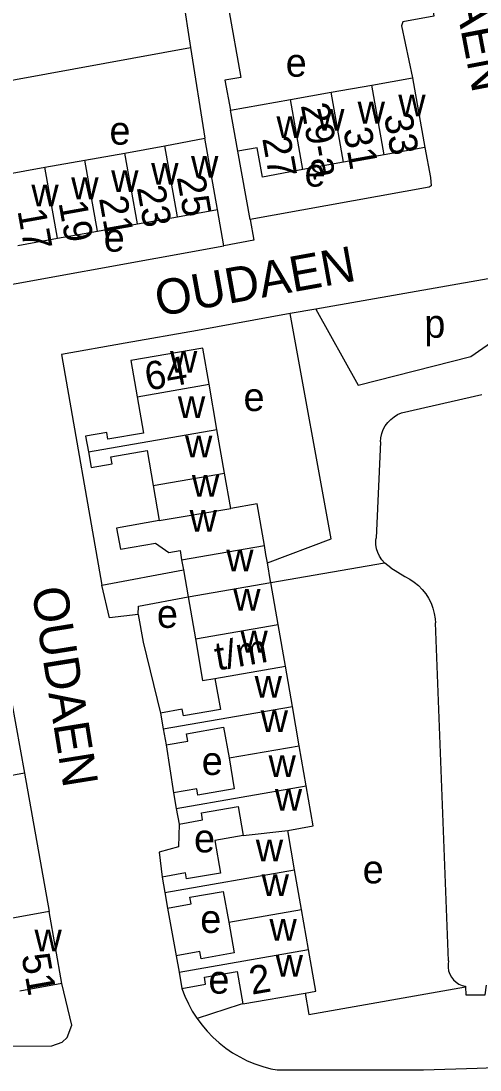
# Model space of a CAD drawing. Extents: x 157794 to 159375, y 380877 to 382306.
# Drawn here: x 158443.4 to 158508.3, y 381266.1 to 381414.5 of the extents above; entities that cross this region are included whole.
import ezdxf

# ---------------------------------------------------------------- set-up
doc = ezdxf.new("R2010")
doc.units = 0
for name, color, linetype in [('BLT_Basislijn', 7, 'Continuous'), ('BLT_Bebouwing', 7, 'Continuous'), ('BLT_Centroide', 7, 'Continuous'), ('BLT_Huisnummer', 7, 'Continuous'), ('BLT_Huisnummer_ tussenligend', 7, 'Continuous'), ('BLT_Huisnummer_reeks', 7, 'Continuous'), ('BLT_Onderverdeling_panden', 7, 'Continuous'), ('BLT_Straatnaam', 7, 'Continuous')]:
    doc.layers.add(name, color=color, linetype=linetype)

msp = doc.modelspace()

# ---------------------------------------------------------------- linework, layer by layer
at = {"layer": 'BLT_Basislijn'}
for p, q in [((158465.74, 381421.18), (158467.36, 381410.72)), ((158467.36, 381410.72), (158469.35, 381397.88)), ((158475.79, 381386.39), (158474.04, 381396.04)), ((158472.07, 381382.65), (158471.15, 381387.8)), ((158509.46, 381378.03), (158485.08, 381373.71)), ((158485.08, 381373.71), (158481.45, 381373.09)), ((158497.19, 381359.04), (158508.53, 381361.64)), ((158494.21, 381354.94), (158493.59, 381341.35)), ((158478.71, 381335.05), (158494.77, 381337.86)), ((158495.69, 381337.15), (158497.67, 381335.92)), ((158454.79, 381334.67), (158466.33, 381336.85)), ((158503.84, 381281.57), (158501.99, 381329.37)), ((158442.03, 381318.28), (158443.84, 381308.11)), ((158463.88, 381312.12), (158464.95, 381305.32)), ((158443.84, 381308.11), (158386.88, 381297.83)), ((158443.84, 381308.11), (158447.34, 381288.52)), ((158464.08, 381289.03), (158465.32, 381282.29)), ((158506.24, 381277.98), (158506.24, 381277.88))]:
    msp.add_line(p, q, dxfattribs=at)
for points in [[(158500.87, 381421.37), (158501.78, 381415.14), (158497.38, 381414.35), (158497.19, 381413.77), (158498.73, 381406.43)], [(158472.71, 381416.28), (158474.45, 381406.5), (158472.22, 381406.1), (158472.99, 381401.84)], [(158422.02, 381402.51), (158422.16, 381402.47), (158467.36, 381410.72)], [(158500.5, 381396.58), (158501.28, 381392.33), (158501.37, 381391.14), (158501.12, 381390.98), (158475.79, 381386.39)], [(158475.79, 381386.39), (158476.32, 381383.48), (158472.07, 381382.65)], [(158433.33, 381372.63), (158433.01, 381375.62), (158472.07, 381382.65)], [(158481.45, 381373.09), (158468.32, 381370.71), (158458.11, 381368.93), (158449.11, 381367.29), (158454.79, 381334.67)], [(158478.22, 381337.84), (158487.26, 381341.23), (158481.45, 381373.09)], [(158485.08, 381373.71), (158491.07, 381362.99), (158507.01, 381367.04), (158515.5, 381372.92)], [(158494.21, 381354.94), (158494.27, 381355.54), (158494.4, 381356.12), (158494.61, 381356.68), (158494.9, 381357.2), (158495.25, 381357.69), (158495.66, 381358.12), (158496.13, 381358.49), (158496.64, 381358.8), (158497.19, 381359.04)], [(158494.77, 381337.86), (158494.39, 381338.29), (158494.08, 381338.77), (158493.84, 381339.29), (158493.67, 381339.85), (158493.57, 381340.42), (158493.56, 381340.99), (158493.59, 381341.35)], [(158495.69, 381337.15), (158494.84, 381337.8), (158494.77, 381337.86)], [(158497.67, 381335.92), (158498.35, 381335.56), (158498.99, 381335.13), (158499.59, 381334.64), (158500.12, 381334.09), (158500.61, 381333.48), (158501.02, 381332.83), (158501.37, 381332.14), (158501.64, 381331.42), (158501.83, 381330.67), (158501.95, 381329.91), (158501.99, 381329.37)], [(158459.96, 381330.54), (158455.86, 381330.06), (158454.79, 381334.67)], [(158459.96, 381330.54), (158459.99, 381331.72), (158467, 381333.02)], [(158459.96, 381330.54), (158460.66, 381326.63), (158463.09, 381316.6)], [(158465.72, 381300.91), (158465.66, 381297.67), (158462.9, 381296.93), (158463.31, 381293.42)], [(158503.84, 381281.57), (158503.77, 381281.09), (158503.77, 381280.61), (158503.85, 381280.13), (158504.02, 381279.67), (158504.25, 381279.25), (158504.55, 381278.87), (158504.91, 381278.54), (158505.32, 381278.28), (158505.76, 381278.09), (158506.24, 381277.98)], [(158391.85, 381269.33), (158447.71, 381269.54), (158449.17, 381270.08), (158449.9, 381270.72), (158450.54, 381272.47), (158449.15, 381278.34)], [(158466.12, 381277.67), (158466.54, 381276.56), (158467.04, 381275.49), (158467.6, 381274.45), (158468.23, 381273.45), (158468.28, 381273.4)], [(158483.58, 381277.01), (158484.1, 381274), (158506.24, 381277.88)], [(158506.24, 381277.88), (158506.31, 381276.75), (158507.67, 381276.75)], [(158507.67, 381276.75), (158509.02, 381276.75), (158509.19, 381278.13)], [(158474.73, 381275.47), (158474.35, 381275.4), (158468.28, 381273.4)], [(158468.28, 381273.4), (158468.93, 381272.5), (158469.69, 381271.6), (158470.52, 381270.75), (158471.39, 381269.96), (158472.32, 381269.23), (158473.3, 381268.57), (158474.32, 381267.97), (158475.37, 381267.44), (158476.46, 381266.99), (158477.58, 381266.61), (158478.72, 381266.3), (158479.58, 381266.13)], [(158479.58, 381266.13), (158500.32, 381266.13), (158507.88, 381266.39)], [(158507.88, 381266.39), (158515.62, 381266.66)]]:
    msp.add_lwpolyline(points, dxfattribs=at)
at = {"layer": 'BLT_Bebouwing'}
for p, q in [((158487.24, 381404.38), (158492.99, 381405.4)), ((158492.99, 381405.4), (158498.73, 381406.43)), ((158498.73, 381406.43), (158500.5, 381396.58)), ((158481.49, 381403.35), (158487.24, 381404.38)), ((158472.99, 381401.84), (158481.49, 381403.35)), ((158474.04, 381396.04), (158472.99, 381401.84)), ((158463.71, 381396.81), (158469.35, 381397.88)), ((158471.15, 381387.8), (158469.35, 381397.88)), ((158458.06, 381395.8), (158463.71, 381396.81)), ((158500.5, 381396.58), (158494.75, 381395.55)), ((158446.75, 381393.78), (158452.4, 381394.79)), ((158452.4, 381394.79), (158458.06, 381395.8)), ((158494.75, 381395.55), (158489, 381394.52)), ((158441.1, 381392.77), (158446.75, 381393.78)), ((158489, 381394.52), (158483.25, 381393.49)), ((158465.5, 381386.79), (158471.15, 381387.8)), ((158459.85, 381385.78), (158465.5, 381386.79)), ((158448.55, 381383.75), (158454.2, 381384.77)), ((158454.2, 381384.77), (158459.85, 381385.78)), ((158442.9, 381382.74), (158448.55, 381383.75)), ((158471.08, 381356.72), (158469.97, 381363.09)), ((158472.16, 381350.53), (158471.08, 381356.72)), ((158473.03, 381345.55), (158472.16, 381350.53)), ((158462.05, 381348.77), (158462.91, 381343.82)), ((158478.01, 381339.03), (158477.8, 381340.28)), ((158478.22, 381337.84), (158478.01, 381339.03)), ((158466.08, 381338.28), (158466.33, 381336.85)), ((158478.68, 381335.22), (158478.22, 381337.84)), ((158466.33, 381336.85), (158467, 381333.02)), ((158478.71, 381335.05), (158478.68, 381335.22)), ((158479.74, 381329.14), (158478.71, 381335.05)), ((158467, 381333.02), (158468.03, 381327.1)), ((158480.77, 381323.23), (158479.74, 381329.14)), ((158481.76, 381317.54), (158480.77, 381323.23)), ((158463.09, 381316.6), (158463.48, 381314.36)), ((158482.73, 381311.98), (158481.76, 381317.54)), ((158463.48, 381314.36), (158463.88, 381312.12)), ((158483.72, 381306.32), (158482.73, 381311.98)), ((158464.95, 381305.32), (158465.33, 381303.11)), ((158465.33, 381303.11), (158465.72, 381300.91)), ((158482.06, 381294.43), (158481.09, 381300.01)), ((158483.04, 381288.82), (158482.06, 381294.43)), ((158463.31, 381293.42), (158463.69, 381291.23)), ((158463.69, 381291.23), (158464.08, 381289.03)), ((158447.34, 381288.52), (158441.39, 381287.46)), ((158449.15, 381278.34), (158447.34, 381288.52)), ((158484.02, 381283.16), (158483.04, 381288.82)), ((158465.32, 381282.29), (158465.72, 381279.98)), ((158465.72, 381279.98), (158466.12, 381277.67)), ((158449.15, 381278.34), (158443.21, 381277.28)), ((158474.73, 381275.47), (158483.58, 381277.01))]:
    msp.add_line(p, q, dxfattribs=at)
for points in [[(158483.25, 381393.49), (158477.52, 381392.38), (158476.77, 381396.55), (158474.04, 381396.04)], [(158469.97, 381363.09), (158469.08, 381368.21), (158458.91, 381366.44), (158459.8, 381361.32)], [(158459.8, 381361.32), (158460.69, 381356.19), (158455.67, 381355.32), (158455.5, 381356.28), (158452.5, 381355.76), (158452.89, 381353.54)], [(158452.89, 381353.54), (158453.27, 381351.33), (158456.26, 381351.85), (158456.09, 381352.83), (158461.19, 381353.72), (158462.05, 381348.77)], [(158477.8, 381340.28), (158476.76, 381346.2), (158473.03, 381345.55)], [(158462.91, 381343.82), (158456.89, 381342.77), (158457.42, 381339.76), (158462.38, 381340.62), (158464.28, 381339.31), (158465.86, 381339.58), (158466.08, 381338.28)], [(158468.03, 381327.1), (158469.06, 381321.19), (158470.8, 381321.5)], [(158470.8, 381321.5), (158471.57, 381317.1), (158466.34, 381316.19), (158466.17, 381317.14), (158463.09, 381316.6)], [(158463.88, 381312.12), (158466.96, 381312.65), (158466.78, 381313.68), (158472.03, 381314.6), (158472.79, 381310.25)], [(158472.79, 381310.25), (158473.54, 381305.9), (158468.39, 381305.01), (158468.24, 381305.89), (158464.95, 381305.32)], [(158481.09, 381300.01), (158484.71, 381300.64), (158483.72, 381306.32)], [(158465.72, 381300.91), (158469.06, 381301.49), (158468.89, 381302.49), (158474.1, 381303.4), (158474.81, 381299.31)], [(158474.81, 381299.31), (158470.77, 381298.6), (158471.58, 381293.98), (158466.77, 381293.14), (158466.62, 381294), (158463.31, 381293.42)], [(158464.08, 381289.03), (158467.42, 381289.61), (158467.26, 381290.55), (158471.98, 381291.38), (158472.74, 381287.03)], [(158472.74, 381287.03), (158473.5, 381282.68), (158468.84, 381281.87), (158468.66, 381282.88), (158465.32, 381282.29)], [(158483.58, 381277.01), (158485.05, 381277.26), (158484.02, 381283.16)], [(158466.12, 381277.67), (158469.47, 381278.25), (158469.3, 381279.25), (158473.93, 381280.06), (158474.73, 381275.47)]]:
    msp.add_lwpolyline(points, dxfattribs=at)
at = {"layer": 'BLT_Onderverdeling_panden'}
for p, q in [((158494.75, 381395.55), (158492.99, 381405.4)), ((158489, 381394.52), (158487.24, 381404.38)), ((158483.25, 381393.49), (158481.49, 381403.35)), ((158465.5, 381386.79), (158463.71, 381396.81)), ((158454.2, 381384.77), (158452.4, 381394.79)), ((158459.85, 381385.78), (158458.06, 381395.8)), ((158448.55, 381383.75), (158446.75, 381393.78)), ((158459.8, 381361.32), (158469.97, 381363.09)), ((158452.89, 381353.54), (158471.08, 381356.72)), ((158462.05, 381348.77), (158472.16, 381350.53)), ((158462.91, 381343.82), (158473.03, 381345.55)), ((158466.08, 381338.28), (158477.8, 381340.28)), ((158467, 381333.02), (158478.71, 381335.05)), ((158468.03, 381327.1), (158479.74, 381329.14)), ((158470.8, 381321.5), (158480.77, 381323.23)), ((158463.48, 381314.36), (158481.76, 381317.54)), ((158472.79, 381310.25), (158482.73, 381311.98)), ((158465.33, 381303.11), (158483.72, 381306.32)), ((158474.81, 381299.31), (158481.09, 381300.01)), ((158463.69, 381291.23), (158482.06, 381294.43)), ((158472.74, 381287.03), (158483.04, 381288.82)), ((158465.72, 381279.98), (158484.02, 381283.16))]:
    msp.add_line(p, q, dxfattribs=at)

# ---------------------------------------------------------------- texts
at = {"layer": 'BLT_Centroide'}
for s, p in [('e', (158480.81, 381406.59)), ('w', (158496.73, 381400.98)), ('w', (158490.98, 381399.97)), ('w', (158479.5, 381397.91)), ('w', (158485.25, 381398.94)), ('e', (158455.88, 381396.98)), ('w', (158467.42, 381392.31)), ('w', (158456.12, 381390.28)), ('w', (158461.78, 381391.3)), ('e', (158483.47, 381391.05)), ('w', (158450.47, 381389.27)), ('w', (158444.83, 381388.27)), ('e', (158455.07, 381381.85)), ('p', (158500.41, 381369.68)), ('w', (158464.44, 381364.75)), ('e', (158474.84, 381359.31)), ('w', (158465.56, 381358.31)), ('w', (158466.57, 381352.75)), ('w', (158467.54, 381347.19)), ('w', (158467.22, 381342.25)), ('w', (158472.4, 381336.66)), ('w', (158473.38, 381331.09)), ('e', (158462.59, 381328.65)), ('w', (158474.4, 381325.16)), ('w', (158476.41, 381318.78)), ('w', (158477.27, 381313.91)), ('e', (158468.93, 381307.85)), ('w', (158478.38, 381307.56)), ('w', (158479.27, 381302.81)), ('e', (158467.84, 381296.9)), ('w', (158476.58, 381295.62)), ('e', (158491.7, 381292.52)), ('w', (158477.4, 381290.72)), ('e', (158468.72, 381285.51)), ('w', (158478.51, 381284.41)), ('w', (158445.27, 381282.91)), ('w', (158479.38, 381279.31)), ('e', (158469.88, 381276.93))]:
    msp.add_text(s, height=4, dxfattribs=at).set_placement(p)
at = {"layer": 'BLT_Huisnummer'}
for s, rotation, p in [('33', 280.139, (158494.69, 381401.11)), ('27', 280.1363, (158477.47, 381397.87)), ('25', 280.1332, (158465.38, 381392.39)), ('19', 280.1332, (158448.66, 381388.78)), ('51', 280.1036, (158443.41, 381282.32))]:
    msp.add_text(s, height=4, rotation=rotation, dxfattribs=at).set_placement(p)
at = {"layer": 'BLT_Huisnummer_ tussenligend'}
for s, rotation, p in [('31', 280.1363, (158488.93, 381399.13)), ('23', 280.1332, (158459.73, 381390.91)), ('21', 280.1332, (158454.38, 381389.41)), ('17', 280.1332, (158442.85, 381387.65))]:
    msp.add_text(s, height=4, rotation=rotation, dxfattribs=at).set_placement(p)
at = {"layer": 'BLT_Huisnummer_reeks'}
for s, rotation, p in [('29-a', 280.1363, (158482.93, 381402.56)), ('64', 9.8892, (158461.24, 381362.18)), ('t/m', 9.8813, (158471.13, 381322.6)), ('2', 9.8815, (158476, 381276.76))]:
    msp.add_text(s, height=4, rotation=rotation, dxfattribs=at).set_placement(p)
at = {"layer": 'BLT_Straatnaam'}
for rotation, p in [(280.7856, (158501.93, 381432.22)), (10.2696, (158462.81, 381372.67)), (279.1299, (158444.86, 381334.1))]:
    msp.add_text('OUDAEN', height=5, rotation=rotation, dxfattribs=at).set_placement(p)

doc.saveas('drawing.dxf')
